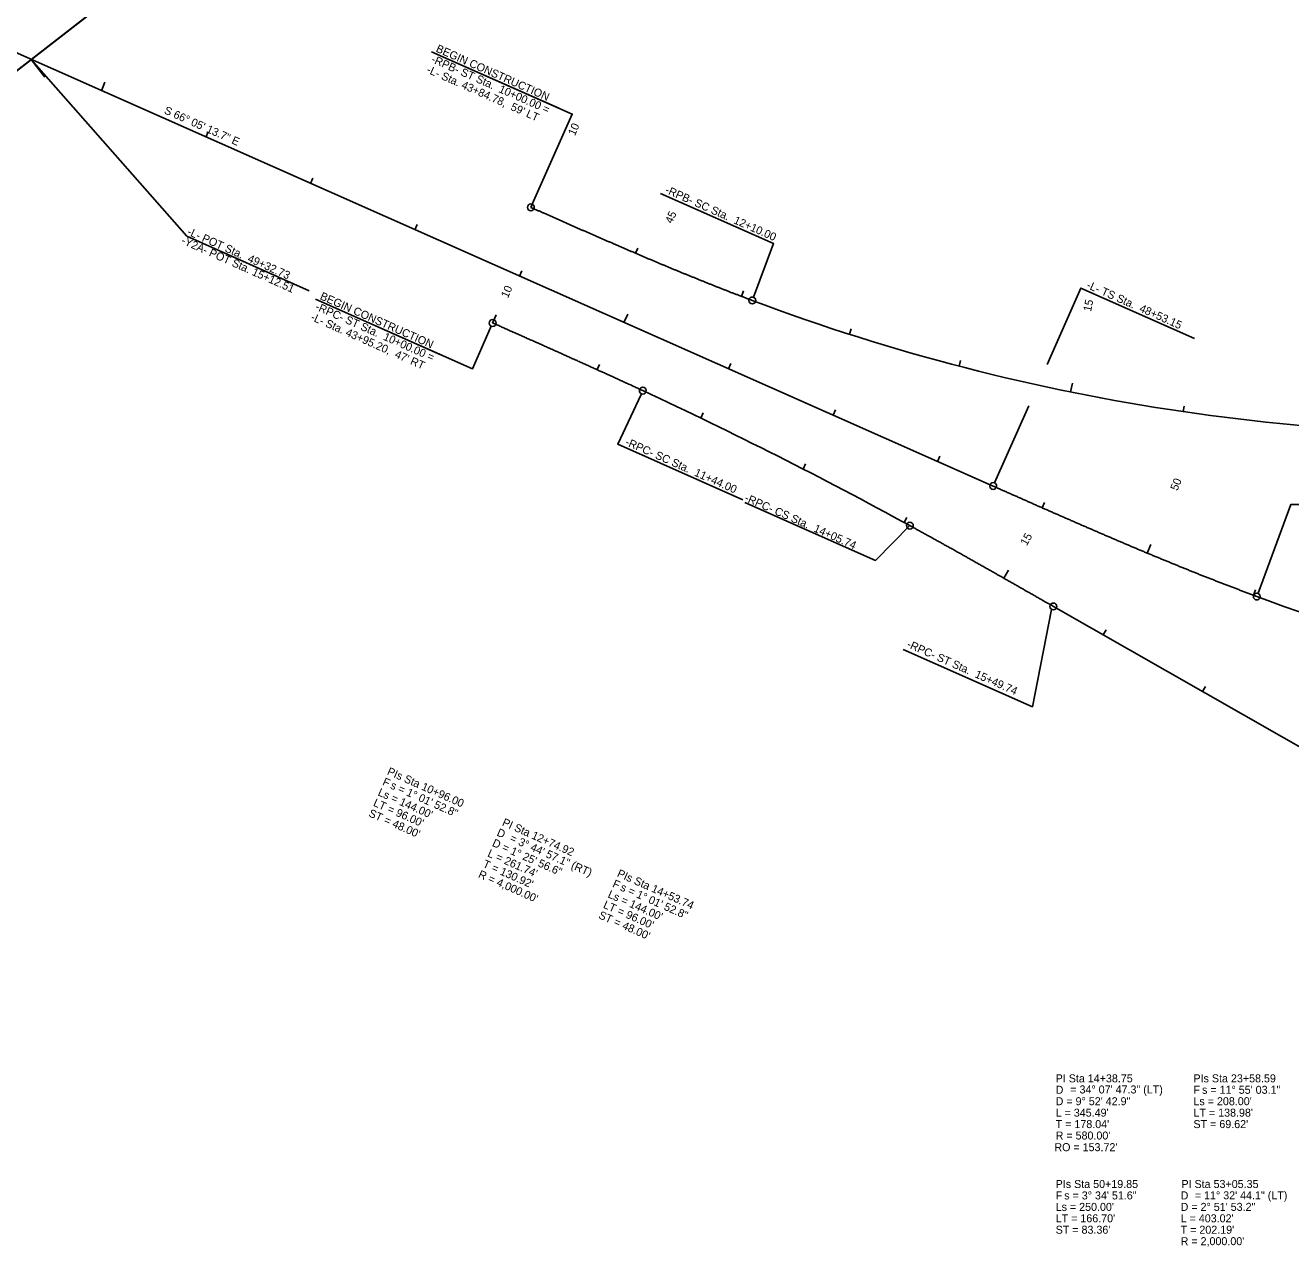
# Model space of a CAD drawing. Extents: x 1636713 to 1642889, y 841520 to 844630.
# Drawn here: x 1639512 to 1640618, y 841961 to 843029 of the extents above; entities that cross this region are included whole.
import ezdxf

# ---------------------------------------------------------------- set-up
doc = ezdxf.new("R2010")
doc.units = 0
for name, color, linetype in [('Exist 4 AWG with gnd feeder circuit in conduit', 7, 'Continuous'), ('Exist 6 AWG with gnd feeder circuit', 7, 'Continuous'), ('Exist 8 AWG with gnd feeder circuit', 7, 'Continuous'), ('Exist 8 AWG with gnd feeder circuit in conduit', 7, 'Continuous'), ('Prop 2 AWG with gnd feeder circuit', 7, 'Continuous'), ('Prop 2 AWG with gnd feeder circuit in conduit', 7, 'Continuous'), ('Prop 4 AWG with gnd feeder circuit', 7, 'Continuous'), ('Prop Berm Ditch Leader', 7, 'Continuous'), ('Prop Clearing and Grubbing', 7, 'Continuous')]:
    doc.layers.add(name, color=color, linetype=linetype)

msp = doc.modelspace()

# ---------------------------------------------------------------- linework, layer by layer
at = {"layer": 'Exist 6 AWG with gnd feeder circuit'}
for p, q in [((1639516.5, 842999.5), (1639652.9, 842845.2)), ((1639977.5, 842957.2), (1639866.6, 843006.4)), ((1639652.9, 842845.2), (1639759.6, 842797.2)), ((1639875.4, 842741.1), (1639765.2, 842790))]:
    msp.add_line(p, q, dxfattribs=at)
for points in [[(1639866.6, 843006.4), (1639989.8, 842951.8), (1639954.8, 842873)], [(1640148.2, 842791.7), (1640165.9, 842838.6), (1640067, 842882.4)], [(1640405.1, 842732.9), (1640434.6, 842799.6), (1640533.8, 842755.6)], [(1639765.2, 842790), (1639902.6, 842729.1), (1639919, 842766.4)], [(1640050, 842706.7), (1640029.6, 842663), (1640139.1, 842614.4)], [(1640359.1, 842629.2), (1640389, 842696.6)], [(1640285, 842591.9), (1640255, 842561.4), (1640140.6, 842612.1)], [(1640589.5, 842532.7), (1640618.3, 842610.5), (1640722.1, 842610.5)], [(1640409, 842518.6), (1640392.2, 842433.5), (1640279.3, 842483.5)]]:
    msp.add_lwpolyline(points, dxfattribs=at)
for centre in [(1639953.6, 842870.2), (1640147.2, 842788.8), (1639920.2, 842769.1), (1640051.5, 842710), (1640357.9, 842626.5), (1640285, 842591.9), (1640588.4, 842529.9), (1640410.5, 842521.2)]:
    msp.add_circle(centre, 3, dxfattribs=at)
at = {"layer": 'Exist 8 AWG with gnd feeder circuit'}
for p, q in [((1638900.9, 843272.5), (1640357.9, 842626.5)), ((1639225.3, 842773.5), (1639731.3, 843166.3)), ((1640410.5, 842521.2), (1640992.2, 842189.1)), ((1640410.5, 842521.2), (1640992.2, 842189.1))]:
    msp.add_line(p, q, dxfattribs=at)
for centre, radius, start, end in [((1640787.7, 844492.4), 1820, 249.3927, 273.9422), ((1638364.5, 839083.1), 4000, 61.3066, 65.0558), ((1638364.5, 839083.1), 4000, 61.3066, 65.0558), ((1641283.4, 844405.3), 2000, 249.6681, 261.2137)]:
    msp.add_arc(centre, radius, start, end, dxfattribs=at)
for points in [[(1639953.6, 842870.2), (1639956.2, 842869.1), (1639958.8, 842867.9), (1639961.4, 842866.8), (1639964, 842865.6), (1639966.6, 842864.5), (1639969.2, 842863.3), (1639971.8, 842862.2), (1639974.4, 842861), (1639977, 842859.9), (1639979.6, 842858.8), (1639982.2, 842857.6), (1639984.8, 842856.5), (1639987.3, 842855.3), (1639989.9, 842854.2), (1639992.5, 842853), (1639995.1, 842851.9), (1639997.7, 842850.7), (1640000.3, 842849.6), (1640002.9, 842848.5), (1640005.5, 842847.3), (1640008.1, 842846.2), (1640010.7, 842845), (1640013.3, 842843.9), (1640015.9, 842842.8), (1640018.5, 842841.6), (1640021.1, 842840.5), (1640023.7, 842839.4), (1640026.3, 842838.2), (1640028.9, 842837.1), (1640031.5, 842836), (1640034.2, 842834.9), (1640036.8, 842833.7), (1640039.4, 842832.6), (1640042, 842831.5), (1640044.6, 842830.4), (1640047.2, 842829.3), (1640049.8, 842828.1), (1640052.4, 842827), (1640055, 842825.9), (1640057.6, 842824.8), (1640060.3, 842823.7), (1640062.9, 842822.6), (1640065.5, 842821.5), (1640068.1, 842820.4), (1640070.7, 842819.3), (1640073.3, 842818.2), (1640076, 842817.1), (1640078.6, 842816), (1640081.2, 842815), (1640083.8, 842813.9), (1640086.4, 842812.8), (1640089.1, 842811.7), (1640091.7, 842810.6), (1640094.3, 842809.6), (1640097, 842808.5), (1640099.6, 842807.4), (1640102.2, 842806.4), (1640104.8, 842805.3), (1640107.5, 842804.3), (1640110.1, 842803.2), (1640112.8, 842802.2), (1640115.4, 842801.1), (1640118, 842800.1), (1640120.7, 842799), (1640123.3, 842798), (1640126, 842797), (1640128.6, 842795.9), (1640131.2, 842794.9), (1640133.9, 842793.9), (1640136.5, 842792.9), (1640139.2, 842791.9), (1640141.9, 842790.9), (1640144.5, 842789.8), (1640147.2, 842788.8)], [(1639920.2, 842769.1), (1639922, 842768.3), (1639923.7, 842767.5), (1639925.5, 842766.8), (1639927.3, 842766), (1639929.1, 842765.2), (1639930.9, 842764.4), (1639932.6, 842763.6), (1639934.4, 842762.8), (1639936.2, 842762), (1639938, 842761.2), (1639939.8, 842760.4), (1639941.5, 842759.6), (1639943.3, 842758.9), (1639945.1, 842758.1), (1639946.9, 842757.3), (1639948.6, 842756.5), (1639950.4, 842755.7), (1639952.2, 842754.9), (1639954, 842754.1), (1639955.8, 842753.3), (1639957.5, 842752.5), (1639959.3, 842751.7), (1639961.1, 842751), (1639962.9, 842750.2), (1639964.6, 842749.4), (1639966.4, 842748.6), (1639968.2, 842747.8), (1639970, 842747), (1639971.8, 842746.2), (1639973.5, 842745.4), (1639975.3, 842744.6), (1639977.1, 842743.8), (1639978.9, 842743), (1639980.6, 842742.2), (1639982.4, 842741.4), (1639984.2, 842740.6), (1639986, 842739.8), (1639987.7, 842739), (1639989.5, 842738.2), (1639991.3, 842737.4), (1639993.1, 842736.6), (1639994.8, 842735.8), (1639996.6, 842735), (1639998.4, 842734.2), (1640000.2, 842733.4), (1640001.9, 842732.6), (1640003.7, 842731.8), (1640005.5, 842731), (1640007.2, 842730.2), (1640009, 842729.4), (1640010.8, 842728.6), (1640012.6, 842727.8), (1640014.3, 842727), (1640016.1, 842726.2), (1640017.9, 842725.4), (1640019.6, 842724.6), (1640021.4, 842723.8), (1640023.2, 842723), (1640025, 842722.2), (1640026.7, 842721.4), (1640028.5, 842720.6), (1640030.3, 842719.7), (1640032, 842718.9), (1640033.8, 842718.1), (1640035.6, 842717.3), (1640037.3, 842716.5), (1640039.1, 842715.7), (1640040.9, 842714.9), (1640042.6, 842714.1), (1640044.4, 842713.2), (1640046.2, 842712.4), (1640047.9, 842711.6), (1640049.7, 842710.8), (1640051.5, 842710)], [(1639920.2, 842769.1), (1639922, 842768.3), (1639923.7, 842767.5), (1639925.5, 842766.8), (1639927.3, 842766), (1639929.1, 842765.2), (1639930.9, 842764.4), (1639932.6, 842763.6), (1639934.4, 842762.8), (1639936.2, 842762), (1639938, 842761.2), (1639939.8, 842760.4), (1639941.5, 842759.6), (1639943.3, 842758.9), (1639945.1, 842758.1), (1639946.9, 842757.3), (1639948.6, 842756.5), (1639950.4, 842755.7), (1639952.2, 842754.9), (1639954, 842754.1), (1639955.8, 842753.3), (1639957.5, 842752.5), (1639959.3, 842751.7), (1639961.1, 842751), (1639962.9, 842750.2), (1639964.6, 842749.4), (1639966.4, 842748.6), (1639968.2, 842747.8), (1639970, 842747), (1639971.8, 842746.2), (1639973.5, 842745.4), (1639975.3, 842744.6), (1639977.1, 842743.8), (1639978.9, 842743), (1639980.6, 842742.2), (1639982.4, 842741.4), (1639984.2, 842740.6), (1639986, 842739.8), (1639987.7, 842739), (1639989.5, 842738.2), (1639991.3, 842737.4), (1639993.1, 842736.6), (1639994.8, 842735.8), (1639996.6, 842735), (1639998.4, 842734.2), (1640000.2, 842733.4), (1640001.9, 842732.6), (1640003.7, 842731.8), (1640005.5, 842731), (1640007.2, 842730.2), (1640009, 842729.4), (1640010.8, 842728.6), (1640012.6, 842727.8), (1640014.3, 842727), (1640016.1, 842726.2), (1640017.9, 842725.4), (1640019.6, 842724.6), (1640021.4, 842723.8), (1640023.2, 842723), (1640025, 842722.2), (1640026.7, 842721.4), (1640028.5, 842720.6), (1640030.3, 842719.7), (1640032, 842718.9), (1640033.8, 842718.1), (1640035.6, 842717.3), (1640037.3, 842716.5), (1640039.1, 842715.7), (1640040.9, 842714.9), (1640042.6, 842714.1), (1640044.4, 842713.2), (1640046.2, 842712.4), (1640047.9, 842711.6), (1640049.7, 842710.8), (1640051.5, 842710)], [(1640357.9, 842626.5), (1640361, 842625.1), (1640364.1, 842623.7), (1640367.1, 842622.3), (1640370.2, 842621), (1640373.3, 842619.6), (1640376.4, 842618.2), (1640379.5, 842616.9), (1640382.6, 842615.5), (1640385.7, 842614.1), (1640388.8, 842612.8), (1640391.9, 842611.4), (1640394.9, 842610), (1640398, 842608.7), (1640401.1, 842607.3), (1640404.2, 842606), (1640407.3, 842604.6), (1640410.4, 842603.2), (1640413.5, 842601.9), (1640416.6, 842600.5), (1640419.7, 842599.2), (1640422.8, 842597.8), (1640425.9, 842596.5), (1640429, 842595.1), (1640432.1, 842593.7), (1640435.2, 842592.4), (1640438.3, 842591.1), (1640441.4, 842589.7), (1640444.5, 842588.4), (1640447.6, 842587), (1640450.7, 842585.7), (1640453.8, 842584.4), (1640456.9, 842583), (1640460, 842581.7), (1640463.1, 842580.4), (1640466.2, 842579), (1640469.3, 842577.7), (1640472.4, 842576.4), (1640475.5, 842575.1), (1640478.6, 842573.7), (1640481.7, 842572.4), (1640484.9, 842571.1), (1640488, 842569.8), (1640491.1, 842568.5), (1640494.2, 842567.2), (1640497.3, 842565.9), (1640500.4, 842564.6), (1640503.6, 842563.3), (1640506.7, 842562), (1640509.8, 842560.7), (1640512.9, 842559.5), (1640516.1, 842558.2), (1640519.2, 842556.9), (1640522.3, 842555.6), (1640525.5, 842554.4), (1640528.6, 842553.1), (1640531.7, 842551.8), (1640534.9, 842550.6), (1640538, 842549.3), (1640541.1, 842548.1), (1640544.3, 842546.8), (1640547.4, 842545.6), (1640550.6, 842544.4), (1640553.7, 842543.1), (1640556.9, 842541.9), (1640560, 842540.7), (1640563.2, 842539.5), (1640566.3, 842538.3), (1640569.5, 842537.1), (1640572.6, 842535.9), (1640575.8, 842534.7), (1640578.9, 842533.5), (1640582.1, 842532.3), (1640585.3, 842531.1), (1640588.4, 842529.9)], [(1640410.5, 842521.2), (1640408.8, 842522.2), (1640407.1, 842523.2), (1640405.4, 842524.1), (1640403.7, 842525.1), (1640402, 842526.1), (1640400.4, 842527), (1640398.7, 842528), (1640397, 842529), (1640395.3, 842529.9), (1640393.6, 842530.9), (1640391.9, 842531.9), (1640390.2, 842532.8), (1640388.5, 842533.8), (1640386.8, 842534.7), (1640385.1, 842535.7), (1640383.4, 842536.7), (1640381.8, 842537.6), (1640380.1, 842538.6), (1640378.4, 842539.6), (1640376.7, 842540.5), (1640375, 842541.5), (1640373.3, 842542.5), (1640371.6, 842543.4), (1640369.9, 842544.4), (1640368.2, 842545.3), (1640366.5, 842546.3), (1640364.8, 842547.3), (1640363.2, 842548.2), (1640361.5, 842549.2), (1640359.8, 842550.1), (1640358.1, 842551.1), (1640356.4, 842552.1), (1640354.7, 842553), (1640353, 842554), (1640351.3, 842554.9), (1640349.6, 842555.9), (1640347.9, 842556.8), (1640346.2, 842557.8), (1640344.5, 842558.8), (1640342.8, 842559.7), (1640341.1, 842560.7), (1640339.4, 842561.6), (1640337.7, 842562.6), (1640336, 842563.5), (1640334.4, 842564.5), (1640332.7, 842565.4), (1640331, 842566.4), (1640329.3, 842567.4), (1640327.6, 842568.3), (1640325.9, 842569.3), (1640324.2, 842570.2), (1640322.5, 842571.2), (1640320.8, 842572.1), (1640319.1, 842573.1), (1640317.4, 842574), (1640315.7, 842574.9), (1640314, 842575.9), (1640312.3, 842576.8), (1640310.6, 842577.8), (1640308.9, 842578.7), (1640307.2, 842579.7), (1640305.5, 842580.6), (1640303.8, 842581.6), (1640302.1, 842582.5), (1640300.4, 842583.4), (1640298.7, 842584.4), (1640297, 842585.3), (1640295.2, 842586.3), (1640293.5, 842587.2), (1640291.8, 842588.1), (1640290.1, 842589.1), (1640288.4, 842590), (1640286.7, 842591), (1640285, 842591.9)], [(1640410.5, 842521.2), (1640408.8, 842522.2), (1640407.1, 842523.2), (1640405.4, 842524.1), (1640403.7, 842525.1), (1640402, 842526.1), (1640400.4, 842527), (1640398.7, 842528), (1640397, 842529), (1640395.3, 842529.9), (1640393.6, 842530.9), (1640391.9, 842531.9), (1640390.2, 842532.8), (1640388.5, 842533.8), (1640386.8, 842534.7), (1640385.1, 842535.7), (1640383.4, 842536.7), (1640381.8, 842537.6), (1640380.1, 842538.6), (1640378.4, 842539.6), (1640376.7, 842540.5), (1640375, 842541.5), (1640373.3, 842542.5), (1640371.6, 842543.4), (1640369.9, 842544.4), (1640368.2, 842545.3), (1640366.5, 842546.3), (1640364.8, 842547.3), (1640363.2, 842548.2), (1640361.5, 842549.2), (1640359.8, 842550.1), (1640358.1, 842551.1), (1640356.4, 842552.1), (1640354.7, 842553), (1640353, 842554), (1640351.3, 842554.9), (1640349.6, 842555.9), (1640347.9, 842556.8), (1640346.2, 842557.8), (1640344.5, 842558.8), (1640342.8, 842559.7), (1640341.1, 842560.7), (1640339.4, 842561.6), (1640337.7, 842562.6), (1640336, 842563.5), (1640334.4, 842564.5), (1640332.7, 842565.4), (1640331, 842566.4), (1640329.3, 842567.4), (1640327.6, 842568.3), (1640325.9, 842569.3), (1640324.2, 842570.2), (1640322.5, 842571.2), (1640320.8, 842572.1), (1640319.1, 842573.1), (1640317.4, 842574), (1640315.7, 842574.9), (1640314, 842575.9), (1640312.3, 842576.8), (1640310.6, 842577.8), (1640308.9, 842578.7), (1640307.2, 842579.7), (1640305.5, 842580.6), (1640303.8, 842581.6), (1640302.1, 842582.5), (1640300.4, 842583.4), (1640298.7, 842584.4), (1640297, 842585.3), (1640295.2, 842586.3), (1640293.5, 842587.2), (1640291.8, 842588.1), (1640290.1, 842589.1), (1640288.4, 842590), (1640286.7, 842591), (1640285, 842591.9)]]:
    msp.add_spline(points, degree=3, dxfattribs=at)
at = {"layer": 'Prop 2 AWG with gnd feeder circuit in conduit'}
for p, q in [((1639578, 842972.3), (1639581.2, 842979.6)), ((1639953.6, 842870.2), (1639956.9, 842877.6)), ((1639920.2, 842769.1), (1639923.4, 842776.4)), ((1640035, 842769.6), (1640038.3, 842776.9)), ((1640425.6, 842708.8), (1640427.2, 842716.6)), ((1640492.5, 842567.9), (1640495.6, 842575.3)), ((1640367.3, 842545.9), (1640371.2, 842552.8))]:
    msp.add_line(p, q, dxfattribs=at)
at = {"layer": 'Prop 4 AWG with gnd feeder circuit'}
for p, q in [((1639669.4, 842931.7), (1639671.4, 842936.3)), ((1639760.8, 842891.2), (1639762.8, 842895.8)), ((1639852.2, 842850.7), (1639854.2, 842855.2)), ((1640045.2, 842830.1), (1640047.2, 842834.7)), ((1639943.6, 842810.1), (1639945.7, 842814.7)), ((1640137.8, 842792.4), (1640139.6, 842797.1)), ((1640232.1, 842759.3), (1640233.7, 842764)), ((1640011.5, 842728.3), (1640013.5, 842732.9)), ((1640126.5, 842729.1), (1640128.5, 842733.6)), ((1640328.2, 842731.4), (1640329.4, 842736.2)), ((1640102.1, 842686), (1640104.2, 842690.5)), ((1640217.9, 842688.5), (1640219.9, 842693.1)), ((1640524.1, 842691.6), (1640524.8, 842696.5)), ((1640524.1, 842691.6), (1640524.8, 842696.5)), ((1640191.6, 842641.4), (1640193.9, 842645.9)), ((1640309.3, 842648), (1640311.3, 842652.6)), ((1640400.7, 842607.5), (1640402.7, 842612.1)), ((1640280, 842594.6), (1640282.4, 842599)), ((1640585.5, 842531), (1640587.2, 842535.7)), ((1640454.1, 842496.3), (1640456.6, 842500.7)), ((1640541, 842446.7), (1640543.5, 842451.1))]:
    msp.add_line(p, q, dxfattribs=at)
at = {"layer": 'Prop Berm Ditch Leader'}
msp.add_line((1639111.6, 842685.2), (1639731.3, 843166.3), dxfattribs=at)
at = {"layer": 'Prop Clearing and Grubbing'}
msp.add_line((1639516.5, 842999.5), (1639528.6, 842984), dxfattribs=at)

# ---------------------------------------------------------------- texts
at = {"layer": 'Exist 4 AWG with gnd feeder circuit in conduit'}
for s, rotation, p in [('10', 66.0871, (1639992.1, 842932.4)), ('45', 66.0871, (1640077, 842855.5)), ('10', 66.0871, (1639933.5, 842790.4)), ('15', 78.5222, (1640443.4, 842778.7)), ('50', 67.3227, (1640518.9, 842621.9)), ('15', 60.3984, (1640387.2, 842573.8))]:
    msp.add_text(s, height=7, rotation=rotation, dxfattribs=at).set_placement(p)
at = {"layer": 'Exist 6 AWG with gnd feeder circuit'}
for s, rotation, p in [('BEGIN CONSTRUCTION', 336.0871, (1639870, 843006.6)), ('-RPB- ST Sta.  10+00.00 =', 336.0871, (1639865.9, 842997.4)), ("-L- Sta. 43+84.78,  59' LT", 336.0871, (1639861.8, 842988.3)), ('-RPB- SC Sta.  12+10.00', 336.0871, (1640070.4, 842883.1)), ('-Y2A- POT Sta. 15+12.51', 335.9473, (1639647.3, 842838.9)), ('-L- POT Sta.  49+32.73', 335.9473, (1639652.5, 842846.6)), ('-L- TS Sta.  48+53.15', 336.0871, (1640438.9, 842799.9)), ('BEGIN CONSTRUCTION', 336.0871, (1639768.6, 842790.1)), ("-L- Sta. 43+95.20,  47' RT", 336.0871, (1639760.5, 842771.9)), ('-RPC- ST Sta.  10+00.00 =', 336.0871, (1639764.5, 842781)), ('-RPC- SC Sta.  11+44.00', 336.0871, (1640035.5, 842662.6)), ('-RPC- CS Sta.  14+05.74', 336.0871, (1640139.9, 842613.7)), ('-RPC- ST Sta.  15+49.74', 336.0871, (1640281.8, 842485.8))]:
    msp.add_text(s, height=7, rotation=rotation, dxfattribs=at).set_placement(p)
at = {"layer": 'Exist 8 AWG with gnd feeder circuit in conduit'}
msp.add_text('S 66%%d 05\' 13.7" E', height=7, rotation=336.0871, dxfattribs=at).set_placement((1639632.3, 842952.6))
at = {"layer": 'Prop 2 AWG with gnd feeder circuit'}
for s, p in [('PIs Sta 10+96.00', (1639827.3, 842374.5)), ('F', (1639823.3, 842365.4)), ('s = 1%%d 01\' 52.8"', (1639830.1, 842362.3)), ("Ls = 144.00'", (1639819.2, 842356.2)), ("LT = 96.00'", (1639815.2, 842347.1)), ("ST = 48.00'", (1639811.1, 842337.9)), ('PI Sta 12+74.92', (1639927.9, 842329.9)), ('D', (1639923.2, 842321)), ('D = 1%%d 25\' 56.6"', (1639919.2, 842311.9)), ('= 3%%d 44\' 57.1" (RT)', (1639934.6, 842316.1)), ("L = 261.74'", (1639915.1, 842302.8)), ("R = 4,000.00'", (1639907, 842284.5)), ("T = 130.92'", (1639911, 842293.6)), ('PIs Sta 14+53.74', (1640028.4, 842285.3)), ('F', (1640024.4, 842276.2)), ("Ls = 144.00'", (1640020.3, 842267)), ('s = 1%%d 01\' 52.8"', (1640031.2, 842273.1)), ("LT = 96.00'", (1640016.3, 842257.9)), ("ST = 48.00'", (1640012.2, 842248.8))]:
    msp.add_text(s, height=7, rotation=336.0871, dxfattribs=at).set_placement(p)
for s, p in [('PI Sta 14+38.75', (1640412.5, 842105)), ('PIs Sta 23+58.59', (1640533, 842105)), ('D', (1640412.5, 842095)), ('= 34%%d 07\' 47.3" (LT)', (1640425.3, 842095.3)), ('F', (1640533, 842095)), ('s = 11%%d 55\' 03.1"', (1640540.5, 842095)), ('D = 9%%d 52\' 42.9"', (1640412.5, 842085)), ("Ls = 208.00'", (1640533, 842085)), ("L = 345.49'", (1640412.5, 842075)), ("LT = 138.98'", (1640533, 842075)), ("T = 178.04'", (1640412.5, 842065)), ("ST = 69.62'", (1640533, 842065)), ("R = 580.00'", (1640412.5, 842055)), ("RO = 153.72'", (1640411.4, 842044.8)), ('PIs Sta 50+19.85', (1640412.5, 842012.6)), ('PI Sta 53+05.35', (1640522.5, 842012.6)), ('F', (1640412.5, 842002.6)), ('s = 3%%d 34\' 51.6"', (1640420, 842002.6)), ('D', (1640521.8, 842002.6)), ('= 11%%d 32\' 44.1" (LT)', (1640534.2, 842002.7)), ("Ls = 250.00'", (1640412.5, 841992.6)), ('D = 2%%d 51\' 53.2"', (1640521.8, 841992.6)), ("ST = 83.36'", (1640412.5, 841972.6)), ("LT = 166.70'", (1640412.5, 841982.6)), ("T = 202.19'", (1640521.8, 841972.6)), ("L = 403.02'", (1640521.8, 841982.6)), ("R = 2,000.00'", (1640521.8, 841962.6))]:
    msp.add_text(s, height=7, dxfattribs=at).set_placement(p)

doc.saveas('drawing.dxf')
